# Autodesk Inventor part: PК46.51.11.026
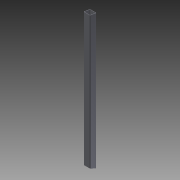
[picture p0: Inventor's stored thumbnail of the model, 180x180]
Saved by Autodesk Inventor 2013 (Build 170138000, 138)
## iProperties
Shininess: 64.0
Length Units: 11269
Angle Units: 11279
Time Units: 11290
Mass Units: 11283
Length Display Precision: 3
Angle Display Precision: 2
Compacted: True
Part Number: PК46.51.11.026
Document SubType Name: Modeling
Created: 2004-07
Material: Steel, Mild
Designer: =<Author>
Manufacturer: Standard
Standards Organization: Custom
Description: pipe
Density: 7.86 g/cm^3
Mass: 1022.08 g
Surface Area: 1304.88 cm^2
Volume: 130.036 cm^3
Density: 0.0
Volumn: 0.0
Area: 0.0
PropertySet Name: Model Information
Control State: 0
Master: False
Checked Out: False
Checked Out Date: 2008-10-15
Last Check In Date: 2008-10-15
Author: PVitaliy
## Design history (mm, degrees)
sketch "Эскиз1"
  geometry: L1 (4, 0)-(26, 0); L2 (30, 4)-(30, 26); L3 (26, 30)-(4, 30); L4 (0, 26)-(0, 4); L5 (2, 26)-(2, 4); L6 (4, 2)-(26, 2); L7 (28, 4)-(28, 26); L8 (26, 28)-(4, 28); A1 r 4 centre (4, 26) between (4, 30) and (0, 26); A2 r 4 centre (26, 26) between (30, 26) and (26, 30); A3 r 4 centre (26, 4) between (26, 0) and (30, 4); A4 r 4 centre (4, 4) between (0, 4) and (4, 0); A5 r 2 centre (4, 26) between (4, 28) and (2, 26); A6 r 2 centre (4, 4) between (2, 4) and (4, 2); A7 r 2 centre (26, 4) between (26, 2) and (28, 4); A8 r 2 centre (26, 26) between (28, 26) and (26, 28); 3 further points
  constraints: 16 end point, 16 point on circle, 8 centre point, 8 tangent, 6 point on line, 4 parallel, 2 equal radius, 2 perpendicular, 1 horizontal, 8 other
  dimensions: "d0" = 30 distance of point (0, 30) point (0, 0); "d1" = 30 distance of point (0, 0) point (30, 0); "d2" = 4 radius of A1; "d3" = 4 radius of A2; "d4" = 2 distance between parallel lines of L1 L6
extrude "Выдавливание1" new body sketch "Эскиз1" distance "d5" = 618; taper "d6" = 0 deg
sketch "Эскиз2"
  geometry: L1 (-618, 22)-(-618, 0) reference; L2 (0, 0)-(0, 22) reference; L3 (0, 26)-(-618, 26) reference; L4 (0, 26)-(0, 22) reference; L5 (0, -4)-(-618, -4) reference; L6 (0, 0)-(0, -4) reference; L7 (0, 26)-(-14, -4); L8 (-618, 22)-(-618, 26) reference; L9 (-618, -4)-(-618, 0) reference; L10 (-618, -4)-(-613, 26)
  constraints: 4 end point, 2 point on line
  dimensions: "d7" = 14 distance from line of L6 L7.end; "d8" = 5 distance from line of L10.end L8
extrude "Выдавливание2" cut sketch "Эскиз2" stored distance "d9" = 10; taper "d10" = 0 deg
body "Solid1"
